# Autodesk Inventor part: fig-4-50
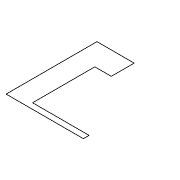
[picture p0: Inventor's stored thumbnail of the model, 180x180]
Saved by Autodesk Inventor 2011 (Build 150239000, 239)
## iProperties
Created: 2004-05
Part Number: fig-4-50
Document SubType Name: Modeling
Designer: CADCIM Technologies
Manufacturer: Standard
Standards Organization: Custom
Density: 1 g/cm^3
Author: CADCIM Technologies
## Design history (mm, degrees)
sketch "Sketch1"
  geometry: L1 (30.083, 49.92)-(16.646, 49.92); L2 (16.646, 49.92)-(16.646, 17.104); L3 (16.646, 17.104)-(44.553, 17.104); L4 (44.553, 17.104)-(44.553, 19.171); L5 (44.553, 19.171)-(24.139, 19.171); L6 (24.139, 19.171)-(24.139, 41.652); L7 (24.139, 41.652)-(30.083, 41.652); L8 (30.083, 41.652)-(30.083, 49.92)
  constraints: 16 end point, 1 horizontal, 1 other
